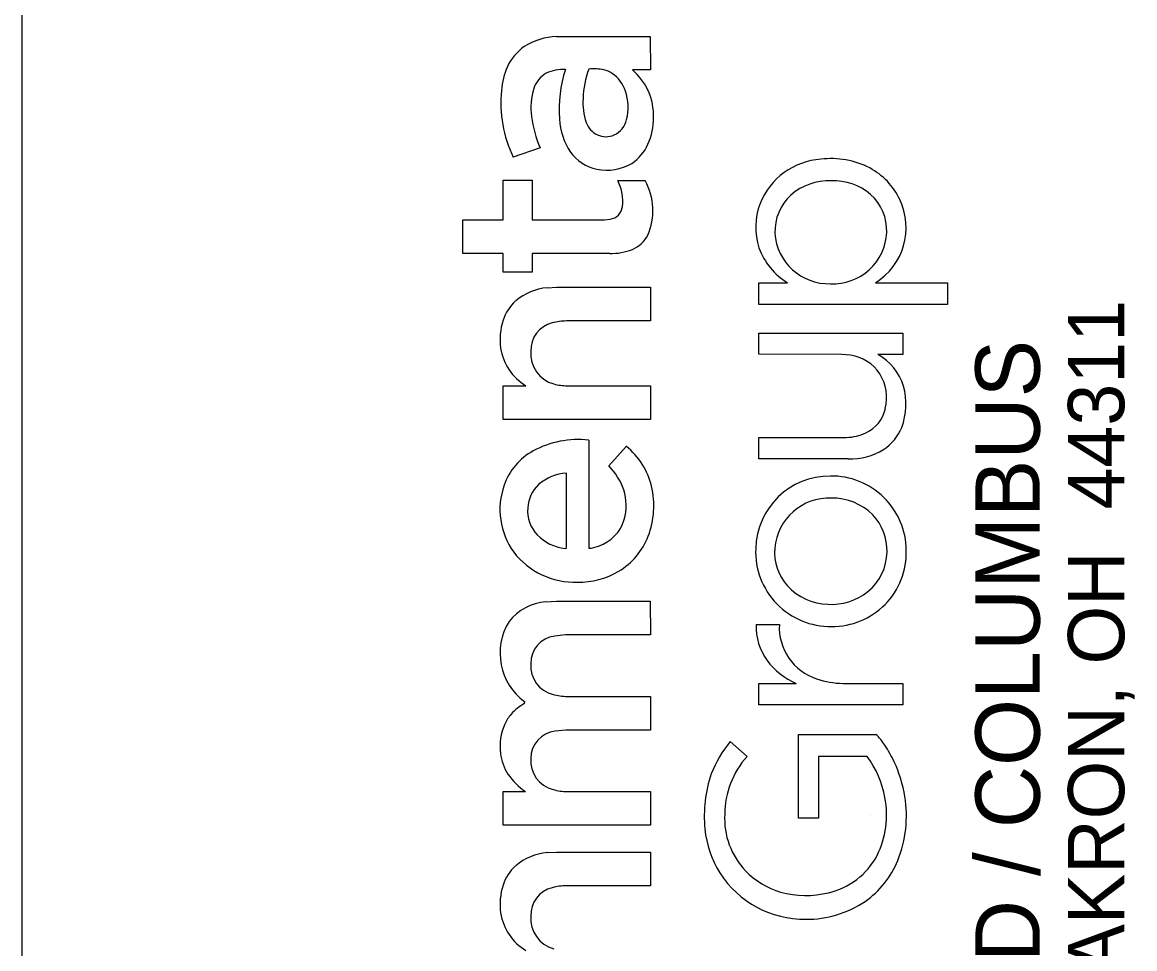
# Model space of a CAD drawing. Extents: x -0.3 to 34, y 0 to 22.
# Drawn here: x 32 to 32.984, y 3.382 to 4.202 of the extents above; entities that cross this region are included whole.
import ezdxf

# ---------------------------------------------------------------- set-up
doc = ezdxf.new("R2010")
doc.units = 0
for name, color, linetype in [('GM_X_Adjacent_County_Text', 7, 'Continuous'), ('GM_X_County', 7, 'Continuous'), ('GM_X_Township', 7, 'Continuous')]:
    doc.layers.add(name, color=color, linetype=linetype)

msp = doc.modelspace()

# ---------------------------------------------------------------- linework, layer by layer
at = {"layer": 'GM_X_Adjacent_County_Text'}
for p, q in [((32.47265, 4.18899), (32.55553, 4.18918)), ((32.55553, 4.18918), (32.55571, 4.15956)), ((32.55571, 4.15956), (32.53971, 4.15956)), ((32.45818, 4.09045), (32.43431, 4.08233)), ((32.42542, 4.02705), (32.42548, 4.06209)), ((32.42548, 4.06209), (32.45108, 4.06209)), ((32.45108, 4.06209), (32.45117, 4.02705)), ((32.52695, 4.06159), (32.5511, 4.06159)), ((32.38964, 4.02701), (32.42542, 4.02705)), ((32.38964, 3.99719), (32.38964, 4.02701)), ((32.45117, 4.02705), (32.51498, 4.02705)), ((32.51498, 4.02705), (32.52005, 4.02749)), ((32.42542, 3.99717), (32.38964, 3.99719)), ((32.42542, 3.98067), (32.42542, 3.99717)), ((32.51969, 3.99718), (32.45108, 3.99715)), ((32.45108, 3.99715), (32.45108, 3.98066)), ((32.45108, 3.98066), (32.42542, 3.98067)), ((32.46439, 3.96686), (32.47289, 3.96732)), ((32.47289, 3.96732), (32.55571, 3.96732)), ((32.55571, 3.96732), (32.55571, 3.93753)), ((32.65152, 3.97113), (32.67709, 3.97115)), ((32.65152, 3.95215), (32.65152, 3.97113)), ((32.75491, 3.97132), (32.81858, 3.97108)), ((32.81858, 3.97108), (32.81843, 3.95215)), ((32.81843, 3.95215), (32.65152, 3.95215)), ((32.55571, 3.93753), (32.4814, 3.93746)), ((32.65152, 3.90801), (32.65153, 3.92672)), ((32.65153, 3.92672), (32.7791, 3.92664)), ((32.7791, 3.92664), (32.77908, 3.90796)), ((32.7249, 3.90796), (32.65152, 3.90801)), ((32.7328, 3.90727), (32.7249, 3.90796)), ((32.77908, 3.90796), (32.75689, 3.90796)), ((32.42542, 3.88016), (32.44552, 3.88021)), ((32.42542, 3.85035), (32.42542, 3.88016)), ((32.48222, 3.88021), (32.55569, 3.88021)), ((32.55569, 3.88021), (32.55571, 3.85045)), ((32.55571, 3.85045), (32.42542, 3.85035)), ((32.50108, 3.83209), (32.50118, 3.73657)), ((32.65154, 3.83443), (32.72905, 3.8345)), ((32.65165, 3.81543), (32.65154, 3.83443)), ((32.51882, 3.80927), (32.53422, 3.82662)), ((32.73073, 3.81543), (32.65165, 3.81543)), ((32.48144, 3.73644), (32.48144, 3.80296)), ((32.48016, 3.73628), (32.48144, 3.73644)), ((32.46329, 3.68915), (32.47259, 3.68968)), ((32.47259, 3.68968), (32.55557, 3.68968)), ((32.55557, 3.68968), (32.55571, 3.65982)), ((32.64932, 3.66907), (32.66978, 3.66907)), ((32.48058, 3.65981), (32.47102, 3.65881)), ((32.55571, 3.65982), (32.48058, 3.65981)), ((32.65152, 3.61699), (32.68476, 3.617)), ((32.65152, 3.598), (32.65152, 3.61699)), ((32.72605, 3.61703), (32.7791, 3.61696)), ((32.7791, 3.61696), (32.77903, 3.598)), ((32.48218, 3.60553), (32.55571, 3.60548)), ((32.55571, 3.60548), (32.55571, 3.57568)), ((32.44443, 3.59922), (32.44455, 3.60072)), ((32.77903, 3.598), (32.65152, 3.598)), ((32.4809, 3.57567), (32.47143, 3.57474)), ((32.55571, 3.57568), (32.4809, 3.57567)), ((32.62636, 3.56548), (32.64114, 3.55241)), ((32.6868, 3.57185), (32.75516, 3.57192)), ((32.6868, 3.49778), (32.6868, 3.57185)), ((32.70448, 3.55241), (32.70432, 3.49775)), ((32.74737, 3.55227), (32.70448, 3.55241)), ((32.42542, 3.49152), (32.42545, 3.52138)), ((32.42545, 3.52138), (32.44515, 3.52138)), ((32.48206, 3.52138), (32.55571, 3.52136)), ((32.55571, 3.52136), (32.55571, 3.49156)), ((32.70432, 3.49775), (32.6868, 3.49778)), ((32.55571, 3.49156), (32.42542, 3.49152)), ((32.46439, 3.46736), (32.47289, 3.46783)), ((32.47289, 3.46783), (32.55571, 3.46783)), ((32.55571, 3.46783), (32.55571, 3.43804)), ((32.55571, 3.43804), (32.4814, 3.43796))]:
    msp.add_line(p, q, dxfattribs=at)
for points in [[(32.47265, 4.18899), (32.55553, 4.18918), (32.55571, 4.15956)], [(32.55571, 4.15956), (32.53971, 4.15956)], [(32.45818, 4.09045), (32.43431, 4.08233)], [(32.51969, 3.99718), (32.45108, 3.99715), (32.45108, 3.98066), (32.42542, 3.98067), (32.42542, 3.99717), (32.38964, 3.99719), (32.38964, 4.02701), (32.42542, 4.02705), (32.42548, 4.06209), (32.45108, 4.06209), (32.45117, 4.02705), (32.51498, 4.02705), (32.52005, 4.02749)], [(32.52695, 4.06159), (32.5511, 4.06159)], [(32.46439, 3.96686), (32.47289, 3.96732), (32.55571, 3.96732), (32.55571, 3.93753), (32.4814, 3.93746)], [(32.75491, 3.97132), (32.81858, 3.97108), (32.81843, 3.95215), (32.65152, 3.95215)], [(32.65152, 3.95215), (32.65152, 3.97113), (32.67709, 3.97115)], [(32.7328, 3.90727), (32.7249, 3.90796), (32.65152, 3.90801), (32.65153, 3.92672), (32.7791, 3.92664), (32.77908, 3.90796), (32.75689, 3.90796)], [(32.42542, 3.85035), (32.42542, 3.88016), (32.44552, 3.88021)], [(32.48222, 3.88021), (32.55569, 3.88021), (32.55571, 3.85045), (32.42542, 3.85035)], [(32.50108, 3.83209), (32.50118, 3.73657)], [(32.73073, 3.81543), (32.65165, 3.81543), (32.65154, 3.83443), (32.72905, 3.8345)], [(32.51882, 3.80927), (32.53422, 3.82662)], [(32.48016, 3.73628), (32.48144, 3.73644), (32.48144, 3.80296)], [(32.46329, 3.68915), (32.47259, 3.68968), (32.55557, 3.68968), (32.55571, 3.65982), (32.48058, 3.65981), (32.47102, 3.65881)], [(32.64932, 3.66907), (32.66978, 3.66907)], [(32.72605, 3.61703), (32.7791, 3.61696), (32.77903, 3.598), (32.65152, 3.598)], [(32.65152, 3.598), (32.65152, 3.61699), (32.68476, 3.617)], [(32.48218, 3.60553), (32.55571, 3.60548), (32.55571, 3.57568), (32.4809, 3.57567), (32.47143, 3.57474)], [(32.44443, 3.59922), (32.44455, 3.60072)], [(32.62636, 3.56548), (32.64114, 3.55241)], [(32.74737, 3.55227), (32.70448, 3.55241), (32.70432, 3.49775), (32.6868, 3.49778), (32.6868, 3.57185), (32.75516, 3.57192)], [(32.42542, 3.49152), (32.42545, 3.52138), (32.44515, 3.52138)], [(32.48206, 3.52138), (32.55571, 3.52136), (32.55571, 3.49156), (32.42542, 3.49152)], [(32.46439, 3.46736), (32.47289, 3.46783), (32.55571, 3.46783), (32.55571, 3.43804), (32.4814, 3.43796)]]:
    msp.add_lwpolyline(points, dxfattribs=at)
for centre, radius, start, end in [((32.47452, 4.13256), 0.05646, 91.89422, 122.63175), ((32.47452, 4.13256), 0.05646, 91.89422, 122.63175), ((32.46847, 4.14467), 0.04302, 124.53704, 155.65938), ((32.46847, 4.14467), 0.04302, 124.53704, 155.65938), ((32.48824, 4.13612), 0.06457, 155.9764, 175.31491), ((32.48824, 4.13612), 0.06457, 155.9764, 175.31491), ((32.47525, 4.1356), 0.024, 119.42515, 161.66285), ((32.47525, 4.1356), 0.024, 119.42515, 161.66285), ((32.47786, 4.12778), 0.03213, 85.38017, 116.62224), ((32.47786, 4.12778), 0.03213, 85.38017, 116.62224), ((32.58787, 4.12508), 0.1129, 162.08213, 184.52847), ((32.58787, 4.12508), 0.1129, 162.08213, 184.52847), ((32.58013, 4.13131), 0.08411, 159.83657, 178.03621), ((32.58013, 4.13131), 0.08411, 159.83657, 178.03621), ((32.50509, 4.10743), 0.05302, 79.66963, 94.23216), ((32.50509, 4.10743), 0.05302, 79.66963, 94.23216), ((32.50892, 4.13643), 0.02384, 56.89129, 76.21489), ((32.50892, 4.13643), 0.02384, 56.89129, 76.21489), ((32.5052, 4.13184), 0.02973, 17.59837, 55.72819), ((32.5052, 4.13184), 0.02973, 17.59837, 55.72819), ((32.50551, 4.11914), 0.05295, 358.07459, 49.76196), ((32.50551, 4.11914), 0.05295, 358.07459, 49.76196), ((32.53639, 4.13078), 0.113, 174.61011, 205.38987), ((32.53639, 4.13078), 0.113, 174.61011, 205.38987), ((32.50758, 4.12645), 0.05758, 163.13694, 188.16749), ((32.50758, 4.12645), 0.05758, 163.13694, 188.16749), ((32.54655, 4.1303), 0.05063, 175.59026, 199.88569), ((32.54655, 4.1303), 0.05063, 175.59026, 199.88569), ((32.4916, 4.1264), 0.04435, 345.94084, 18.99188), ((32.4916, 4.1264), 0.04435, 345.94084, 18.99188), ((32.54725, 4.12973), 0.09735, 186.75982, 203.79807), ((32.54725, 4.12973), 0.09735, 186.75982, 203.79807), ((32.53279, 4.11874), 0.05752, 182.56764, 213.71437), ((32.53279, 4.11874), 0.05752, 182.56764, 213.71437), ((32.51521, 4.11994), 0.01989, 295.28829, 347.46387), ((32.51521, 4.11994), 0.01989, 295.28829, 347.46387), ((32.50187, 4.11678), 0.05657, 336.01604, 0.59505), ((32.50187, 4.11678), 0.05657, 336.01604, 0.59505), ((32.51642, 4.11886), 0.01841, 198.28436, 293.30806), ((32.51642, 4.11886), 0.01841, 198.28436, 293.30806), ((32.51487, 4.10782), 0.03656, 215.06685, 259.81327), ((32.51487, 4.10782), 0.03656, 215.06685, 259.81327), ((32.51752, 4.10969), 0.03938, 303.44357, 336.18), ((32.51752, 4.10969), 0.03938, 303.44357, 336.18), ((32.51753, 4.1131), 0.04227, 257.52557, 300.88195), ((32.51753, 4.1131), 0.04227, 257.52557, 300.88195), ((32.71081, 4.01825), 0.06243, 93.98662, 158.31194), ((32.71081, 4.01825), 0.06243, 93.98662, 158.31194), ((32.71557, 4.0065), 0.07459, 62.68889, 97.01346), ((32.71557, 4.0065), 0.07459, 62.68889, 97.01346), ((32.72123, 4.01914), 0.06076, 25.06574, 61.96022), ((32.72123, 4.01914), 0.06076, 25.06574, 61.96022), ((32.48625, 4.04199), 0.04518, 10.15449, 25.72303), ((32.48625, 4.04199), 0.04518, 10.15449, 25.72303), ((32.50302, 4.03506), 0.05491, 336.58903, 28.89913), ((32.50302, 4.03506), 0.05491, 336.58903, 28.89913), ((32.71379, 4.01017), 0.05134, 87.89653, 131.18123), ((32.71379, 4.01017), 0.05134, 87.89653, 131.18123), ((32.7175, 4.01023), 0.05127, 49.90886, 92.03625), ((32.7175, 4.01023), 0.05127, 49.90886, 92.03625), ((32.49573, 4.04365), 0.03556, 351.91398, 10.20594), ((32.49573, 4.04365), 0.03556, 351.91398, 10.20594), ((32.7092, 4.01674), 0.04338, 132.32887, 182.09489), ((32.7092, 4.01674), 0.04338, 132.32887, 182.09489), ((32.72154, 4.01733), 0.04327, 358.04871, 47.94467), ((32.72154, 4.01733), 0.04327, 358.04871, 47.94467), ((32.7245, 4.02004), 0.05743, 301.97764, 25.64176), ((32.7245, 4.02004), 0.05743, 301.97764, 25.64176), ((32.51837, 4.04001), 0.01263, 277.61423, 353.79181), ((32.51837, 4.04001), 0.01263, 277.61423, 353.79181), ((32.70695, 4.02016), 0.05815, 158.65601, 198.17101), ((32.70695, 4.02016), 0.05815, 158.65601, 198.17101), ((32.71717, 4.01801), 0.04766, 267.31494, 357.4019), ((32.71717, 4.01801), 0.04766, 267.31494, 357.4019), ((32.52913, 4.02612), 0.02749, 292.68889, 332.05977), ((32.52913, 4.02612), 0.02749, 292.68889, 332.05977), ((32.71352, 4.01815), 0.04776, 183.59741, 271.7045), ((32.71352, 4.01815), 0.04776, 183.59741, 271.7045), ((32.52088, 4.04856), 0.05139, 268.67266, 291.52354), ((32.52088, 4.04856), 0.05139, 268.67266, 291.52354), ((32.7103, 4.02433), 0.0627, 200.83985, 238.01619), ((32.7103, 4.02433), 0.0627, 200.83985, 238.01619), ((32.46871, 3.91716), 0.04988, 94.97056, 130.22484), ((32.46871, 3.91716), 0.04988, 94.97056, 130.22484), ((32.46348, 3.92551), 0.04016, 132.22383, 161.68229), ((32.46348, 3.92551), 0.04016, 132.22383, 161.68229), ((32.47872, 3.92108), 0.05602, 162.27398, 187.79173), ((32.47872, 3.92108), 0.05602, 162.27398, 187.79173), ((32.48108, 3.89145), 0.04601, 89.60515, 105.33026), ((32.48108, 3.89145), 0.04601, 89.60515, 105.33026), ((32.47482, 3.91155), 0.02498, 103.68683, 182.21395), ((32.47482, 3.91155), 0.02498, 103.68683, 182.21395), ((32.47027, 3.9209), 0.04763, 188.96462, 238.69865), ((32.47027, 3.9209), 0.04763, 188.96462, 238.69865), ((32.47735, 3.90846), 0.02757, 175.58441, 255.13816), ((32.47735, 3.90846), 0.02757, 175.58441, 255.13816), ((32.72711, 3.86998), 0.03772, 33.50082, 81.32954), ((32.72711, 3.86998), 0.03772, 33.50082, 81.32954), ((32.73239, 3.86485), 0.04959, 17.62209, 60.38974), ((32.73239, 3.86485), 0.04959, 17.62209, 60.38974), ((32.72414, 3.8695), 0.04048, 346.56179, 31.75389), ((32.72414, 3.8695), 0.04048, 346.56179, 31.75389), ((32.48183, 3.92235), 0.04215, 254.08913, 270.52838), ((32.48183, 3.92235), 0.04215, 254.08913, 270.52838), ((32.72343, 3.86415), 0.05838, 339.16197, 15.61485), ((32.72343, 3.86415), 0.05838, 339.16197, 15.61485), ((32.73371, 3.86616), 0.03042, 294.63214, 348.48625), ((32.73371, 3.86616), 0.03042, 294.63214, 348.48625), ((32.72747, 3.88081), 0.04633, 271.95199, 294.08943), ((32.72747, 3.88081), 0.04633, 271.95199, 294.08943), ((32.739, 3.85901), 0.04201, 303.10391, 338.15613), ((32.739, 3.85901), 0.04201, 303.10391, 338.15613), ((32.49176, 3.74874), 0.08387, 83.62118, 118.28448), ((32.49176, 3.74874), 0.08387, 83.62118, 118.28448), ((32.47894, 3.77368), 0.05583, 118.82935, 160.62242), ((32.47894, 3.77368), 0.05583, 118.82935, 160.62242), ((32.49399, 3.7763), 0.06443, 13.53275, 51.36266), ((32.49399, 3.7763), 0.06443, 13.53275, 51.36266), ((32.7321, 3.87256), 0.05715, 268.62699, 301.47779), ((32.7321, 3.87256), 0.05715, 268.62699, 301.47779), ((32.48033, 3.77018), 0.05485, 19.0387, 45.44322), ((32.48033, 3.77018), 0.05485, 19.0387, 45.44322), ((32.4844, 3.76071), 0.04236, 94.01311, 130.88062), ((32.4844, 3.76071), 0.04236, 94.01311, 130.88062), ((32.71435, 3.73484), 0.06552, 89.48213, 178.77752), ((32.71435, 3.73484), 0.06552, 89.48213, 178.77752), ((32.71582, 3.73414), 0.06623, 0.42265, 90.7613), ((32.71582, 3.73414), 0.06623, 0.42265, 90.7613), ((32.48697, 3.77074), 0.06438, 160.52138, 215.78155), ((32.48697, 3.77074), 0.06438, 160.52138, 215.78155), ((32.47703, 3.7709), 0.02985, 132.98553, 177.1802), ((32.47703, 3.7709), 0.02985, 132.98553, 177.1802), ((32.48289, 3.77384), 0.0758, 339.35431, 13.37708), ((32.48289, 3.77384), 0.0758, 339.35431, 13.37708), ((32.48724, 3.77433), 0.04701, 344.60723, 17.00675), ((32.48724, 3.77433), 0.04701, 344.60723, 17.00675), ((32.71397, 3.73244), 0.04846, 87.68827, 175.01696), ((32.71397, 3.73244), 0.04846, 87.68827, 175.01696), ((32.71659, 3.73036), 0.05052, 44.91202, 90.75914), ((32.71659, 3.73036), 0.05052, 44.91202, 90.75914), ((32.47824, 3.76966), 0.03114, 175.00138, 223.2876), ((32.47824, 3.76966), 0.03114, 175.00138, 223.2876), ((32.49895, 3.77177), 0.03504, 288.01084, 343.55364), ((32.49895, 3.77177), 0.03504, 288.01084, 343.55364), ((32.71955, 3.73452), 0.04549, 358.32279, 43.83486), ((32.71955, 3.73452), 0.04549, 358.32279, 43.83486), ((32.48546, 3.77826), 0.04232, 225.06454, 262.79701), ((32.48546, 3.77826), 0.04232, 225.06454, 262.79701), ((32.49548, 3.76982), 0.0626, 300.94393, 338.73223), ((32.49548, 3.76982), 0.0626, 300.94393, 338.73223), ((32.48908, 3.77516), 0.06872, 217.74341, 271.65606), ((32.48908, 3.77516), 0.06872, 217.74341, 271.65606), ((32.50129, 3.75678), 0.02021, 269.70042, 294.87295), ((32.50129, 3.75678), 0.02021, 269.70042, 294.87295), ((32.71483, 3.7334), 0.06606, 177.53728, 270.94524), ((32.71483, 3.7334), 0.06606, 177.53728, 270.94524), ((32.71085, 3.73311), 0.0453, 175.51467, 221.42047), ((32.71085, 3.73311), 0.0453, 175.51467, 221.42047), ((32.71671, 3.73271), 0.06536, 269.30834, 1.67905), ((32.71671, 3.73271), 0.06536, 269.30834, 1.67905), ((32.71931, 3.73374), 0.04572, 308.90382, 359.30947), ((32.71931, 3.73374), 0.04572, 308.90382, 359.30947), ((32.49204, 3.77702), 0.07055, 269.20529, 300.33566), ((32.49204, 3.77702), 0.07055, 269.20529, 300.33566), ((32.71399, 3.73734), 0.05046, 222.66255, 268.37331), ((32.71399, 3.73734), 0.05046, 222.66255, 268.37331), ((32.71567, 3.73859), 0.05178, 266.55312, 308.67253), ((32.71567, 3.73859), 0.05178, 266.55312, 308.67253), ((32.46638, 3.64404), 0.04521, 93.91118, 142.30723), ((32.46638, 3.64404), 0.04521, 93.91118, 142.30723), ((32.47585, 3.64373), 0.05319, 148.28793, 233.9556), ((32.47585, 3.64373), 0.05319, 148.28793, 233.9556), ((32.69878, 3.66662), 0.04952, 177.16211, 216.28024), ((32.69878, 3.66662), 0.04952, 177.16211, 216.28024), ((32.71735, 3.66638), 0.04764, 176.76988, 252.15044), ((32.71735, 3.66638), 0.04764, 176.76988, 252.15044), ((32.47384, 3.63499), 0.02399, 96.75763, 181.6251), ((32.47384, 3.63499), 0.02399, 96.75763, 181.6251), ((32.47577, 3.63241), 0.02597, 175.81573, 256.16716), ((32.47577, 3.63241), 0.02597, 175.81573, 256.16716), ((32.70975, 3.67555), 0.06366, 216.91526, 246.88619), ((32.70975, 3.67555), 0.06366, 216.91526, 246.88619), ((32.7269, 3.69175), 0.07473, 251.13884, 269.34694), ((32.7269, 3.69175), 0.07473, 251.13884, 269.34694), ((32.4817, 3.65053), 0.04501, 254.34629, 270.61033), ((32.4817, 3.65053), 0.04501, 254.34629, 270.61033), ((32.4638, 3.56267), 0.04137, 117.91625, 139.24296), ((32.4638, 3.56267), 0.04137, 117.91625, 139.24296), ((32.46194, 3.56452), 0.03875, 139.52447, 154.84698), ((32.46194, 3.56452), 0.03875, 139.52447, 154.84698), ((32.47144, 3.5612), 0.04877, 156.06382, 187.3493), ((32.47144, 3.5612), 0.04877, 156.06382, 187.3493), ((32.47421, 3.55056), 0.02434, 96.5532, 179.94902), ((32.47421, 3.55056), 0.02434, 96.5532, 179.94902), ((32.70163, 3.50187), 0.09855, 139.79476, 159.13696), ((32.70163, 3.50187), 0.09855, 139.79476, 159.13696), ((32.72498, 3.53937), 0.04438, 30.98913, 47.16099), ((32.72498, 3.53937), 0.04438, 30.98913, 47.16099), ((32.46461, 3.55974), 0.04181, 186.5579, 213.38846), ((32.46461, 3.55974), 0.04181, 186.5579, 213.38846), ((32.67091, 3.50018), 0.11106, 25.30315, 33.96179), ((32.67091, 3.50018), 0.11106, 25.30315, 33.96179), ((32.47608, 3.54863), 0.02628, 175.722, 255.78627), ((32.47608, 3.54863), 0.02628, 175.722, 255.78627), ((32.69899, 3.50079), 0.07753, 138.25804, 179.70064), ((32.69899, 3.50079), 0.07753, 138.25804, 179.70064), ((32.67889, 3.50099), 0.08556, 10.07509, 36.83189), ((32.67889, 3.50099), 0.08556, 10.07509, 36.83189), ((32.6704, 3.49987), 0.11166, 8.80339, 25.33484), ((32.6704, 3.49987), 0.11166, 8.80339, 25.33484), ((32.47886, 3.57078), 0.0598, 214.70433, 235.68724), ((32.47886, 3.57078), 0.0598, 214.70433, 235.68724), ((32.7187, 3.49968), 0.11536, 161.14379, 185.62812), ((32.7187, 3.49968), 0.11536, 161.14379, 185.62812), ((32.48195, 3.56518), 0.0438, 253.66719, 270.14979), ((32.48195, 3.56518), 0.0438, 253.66719, 270.14979), ((32.68425, 3.50057), 0.08036, 333.46689, 11.03668), ((32.68425, 3.50057), 0.08036, 333.46689, 11.03668), ((32.67564, 3.49977), 0.10649, 338.28866, 9.28548), ((32.67564, 3.49977), 0.10649, 338.28866, 9.28548), ((32.68811, 3.49732), 0.06676, 176.66577, 223.6912), ((32.68811, 3.49732), 0.06676, 176.66577, 223.6912), ((32.69336, 3.49699), 0.08987, 185.50773, 212.01294), ((32.69336, 3.49699), 0.08987, 185.50773, 212.01294), ((32.46871, 3.41767), 0.04988, 94.97056, 130.22484), ((32.46871, 3.41767), 0.04988, 94.97056, 130.22484), ((32.69868, 3.49547), 0.0652, 282.88151, 331.81475), ((32.69868, 3.49547), 0.0652, 282.88151, 331.81475), ((32.46348, 3.42602), 0.04016, 132.22383, 161.68229), ((32.46348, 3.42602), 0.04016, 132.22383, 161.68229), ((32.69835, 3.49168), 0.08241, 305.03061, 337.67573), ((32.69835, 3.49168), 0.08241, 305.03061, 337.67573), ((32.69211, 3.49748), 0.08908, 212.70222, 270.71399), ((32.69211, 3.49748), 0.08908, 212.70222, 270.71399), ((32.69045, 3.50011), 0.07039, 224.02147, 253.88), ((32.69045, 3.50011), 0.07039, 224.02147, 253.88), ((32.47872, 3.42158), 0.05602, 162.27398, 187.79173), ((32.47872, 3.42158), 0.05602, 162.27398, 187.79173), ((32.47482, 3.41206), 0.02498, 103.68683, 182.21395), ((32.47482, 3.41206), 0.02498, 103.68683, 182.21395), ((32.48108, 3.39196), 0.04601, 89.60515, 105.33026), ((32.48108, 3.39196), 0.04601, 89.60515, 105.33026), ((32.69318, 3.51254), 0.08309, 254.45353, 283.9512), ((32.69318, 3.51254), 0.08309, 254.45353, 283.9512), ((32.69429, 3.49979), 0.09138, 269.3273, 304.19632), ((32.69429, 3.49979), 0.09138, 269.3273, 304.19632), ((32.47027, 3.42141), 0.04763, 188.96462, 238.69865), ((32.47027, 3.42141), 0.04763, 188.96462, 238.69865), ((32.47735, 3.40897), 0.02757, 175.58441, 255.13816), ((32.47735, 3.40897), 0.02757, 175.58441, 255.13816)]:
    msp.add_arc(centre, radius, start, end, dxfattribs=at)
at = {"layer": 'GM_X_County'}
msp.add_line((32, 0.5), (32, 21.5), dxfattribs=at)
at = {"layer": 'GM_X_Township'}
msp.add_line((32.75, 3.5), (32.75, 3.5), dxfattribs=at)

# ---------------------------------------------------------------- texts
at = {"layer": 'GM_X_Adjacent_County_Text'}
for s, height, p in [('450 GRANT ST., AKRON, OH  44311', 0.0498462, (32.97489, 2.83738)), ('AKRON / CLEVELAND / COLUMBUS', 0.056969, (32.90012, 2.638))]:
    msp.add_text(s, height=height, rotation=90, dxfattribs=at).set_placement(p)

doc.saveas('drawing.dxf')
